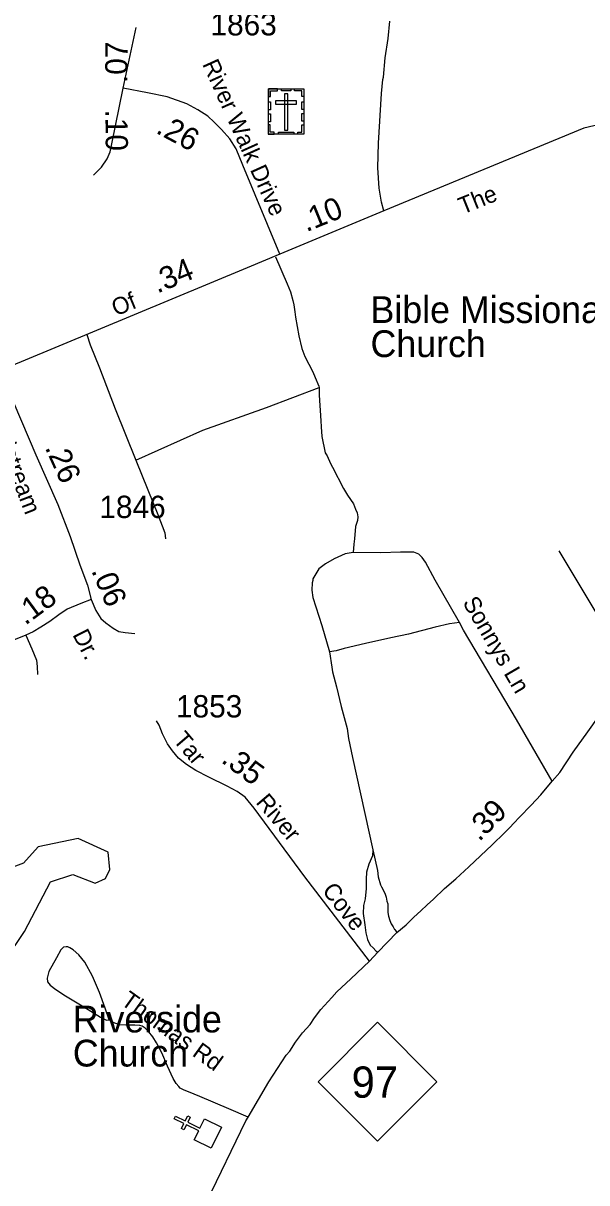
# Model space of a CAD drawing. Extents: x 2220236 to 2384410, y 720751 to 894131.
# Drawn here: x 2329960 to 2333123, y 774971 to 781470 of the extents above; entities that cross this region are included whole.
import ezdxf

# ---------------------------------------------------------------- set-up
doc = ezdxf.new("R2010")
doc.units = 0
for name, color, linetype in [('Exist Cultural Cemetery CELL', 7, 'Continuous'), ('Exist Cultural Church CELL', 7, 'Continuous'), ('Exist Cultural Church Label', 7, 'Continuous'), ('Exist Hydrographic Lake Shore', 7, 'Continuous'), ('Exist Road Non-System Type 51', 7, 'Continuous'), ('Exist Road Non-System Type 51 Label', 7, 'Continuous'), ('Exist Road Primary NC Attributed', 7, 'Continuous'), ('Exist Road Primary NC Service Mileage Hundredths English Label', 7, 'Continuous'), ('Exist Road Primary NC Shield CELL', 7, 'Continuous'), ('Exist Road Primary NC Shield Number Label', 7, 'Continuous'), ('Exist Road Secondary Mileage Hundredths English Label', 7, 'Continuous'), ('Exist Road Secondary Type 51 Attributed', 7, 'Continuous'), ('Exist Road Secondary Type 51 Label', 7, 'Continuous'), ('Exist Road Secondary Type 51 Number Label', 7, 'Continuous')]:
    doc.layers.add(name, color=color, linetype=linetype)

msp = doc.modelspace()

# ---------------------------------------------------------------- linework, layer by layer
at = {"layer": 'Exist Cultural Cemetery CELL'}
for points in [[(2331336, 781103.1), (2331535.1, 781103.1), (2331535.1, 780848.5), (2331336, 780848.5)], [(2331336, 781059.8), (2331347.3, 781059.8), (2331347.3, 781092), (2331387.9, 781092), (2331387.9, 781103.1), (2331336, 781103.1)], [(2331410.1, 781103.1), (2331461.9, 781103.1), (2331461.9, 781091.7), (2331410.1, 781091.7)], [(2331445, 781073.8), (2331426.3, 781073.8), (2331426.3, 780871), (2331445, 780871)], [(2331535.1, 781059.7), (2331523.8, 781059.7), (2331523.8, 781091.9), (2331483.2, 781091.9), (2331483.2, 781103.1), (2331535.1, 781103.1)], [(2331336, 780985.6), (2331336, 781028.9), (2331347.4, 781028.9), (2331347.4, 780985.6)], [(2331376.8, 781035), (2331376.8, 781016.4), (2331494.5, 781016.4), (2331494.5, 781035)], [(2331523.7, 780986.7), (2331523.7, 781030), (2331535.1, 781030), (2331535.1, 780986.7)], [(2331336, 780918.4), (2331336, 780961.7), (2331347.3, 780961.7), (2331347.3, 780918.4)], [(2331523.7, 780920.7), (2331523.7, 780964.1), (2331535.1, 780964.1), (2331535.1, 780920.7)], [(2331369.1, 780848.5), (2331369.1, 780860), (2331347.1, 780860), (2331347.1, 780900.4), (2331335.9, 780900.4), (2331335.9, 780848.5)], [(2331393.4, 780860), (2331478.3, 780860), (2331478.3, 780848.6), (2331393.4, 780848.6)], [(2331501.9, 780848.5), (2331501.9, 780860), (2331523.9, 780860), (2331523.9, 780900.4), (2331535.1, 780900.4), (2331535.1, 780848.5)]]:
    msp.add_lwpolyline(points, close=True, dxfattribs=at)
at = {"layer": 'Exist Cultural Church CELL'}
msp.add_lwpolyline([(2330920.2, 775211.9), (2330945.1, 775263.2), (2330876.7, 775296.6), (2330862.6, 775267.8), (2330848.3, 775274.8), (2330862.3, 775303.6), (2330808.3, 775329.9), (2330815.3, 775344.4), (2330869.4, 775318), (2330883.4, 775346.7), (2330897.8, 775339.7), (2330883.7, 775311), (2330952.1, 775277.6), (2330977.5, 775329.3), (2331073.2, 775282.6), (2331015.9, 775165.2)], close=True, dxfattribs=at)
at = {"layer": 'Exist Hydrographic Lake Shore'}
msp.add_lwpolyline([(2329745, 776051.7), (2329967, 776379.1), (2330114.1, 776657.5), (2330238.1, 776698.7), (2330364, 776651.3), (2330422.1, 776676.7), (2330446.1, 776726.9), (2330437, 776825), (2330269.1, 776900.2), (2330045, 776854.9), (2329962.9, 776762.9), (2329805.1, 776704)], dxfattribs=at)
at = {"layer": 'Exist Road Non-System Type 51'}
msp.add_line((2332045, 776391), (2332056.4, 776374.2), dxfattribs=at)
for points in [[(2331375.6, 780160.2), (2331442.6, 780008.8), (2331460.2, 779965.6), (2331474.2, 779915.3), (2331478.4, 779891.4), (2331485, 779853.3), (2331489.2, 779823.5), (2331507.7, 779719), (2331523.7, 779647.3), (2331540.6, 779602.7), (2331585.9, 779515.7), (2331598.3, 779484.3), (2331618.9, 779435.2), (2331621.1, 779429)], [(2330317.1, 779724.8), (2330336.1, 779667.9), (2330387.8, 779538.6), (2330477.3, 779309.4), (2330592.8, 779021.5)], [(2330592.8, 779021.5), (2330968.3, 779188.7), (2331324.8, 779316.3), (2331621.1, 779429)], [(2331621.1, 779429), (2331621.7, 779385.3), (2331631.4, 779241.3), (2331631.8, 779207.3), (2331636.4, 779153.3), (2331655.3, 779061.6), (2331665.6, 779045.6), (2331684, 779002), (2331696.2, 778982.1), (2331757.5, 778862.7), (2331779.8, 778825), (2331813.4, 778776.6), (2331825.7, 778746.7), (2331833.8, 778726.3), (2331837.9, 778704.5), (2331836.5, 778682.7), (2331825.7, 778648.7), (2331820.2, 778580.7), (2331816.1, 778550.8), (2331812.1, 778503.9)], [(2330592.8, 779021.5), (2330659.9, 778854.3), (2330715.1, 778717.3), (2330754.7, 778613.9), (2330759.8, 778581.1)], [(2331812.1, 778503.9), (2331767.2, 778495.7), (2331706, 778468.5), (2331657.1, 778439.9), (2331618.5, 778411.5), (2331586.4, 778357), (2331585, 778346.1), (2331582.3, 778333.8), (2331581, 778293), (2331586.4, 778252.2), (2331636.7, 778094.4), (2331679.1, 777947.5)], [(2332408.1, 778110.8), (2332271.5, 778348.8), (2332218.5, 778449.5), (2332199.5, 778476.7), (2332180.5, 778494.4), (2332153.3, 778505.2), (2332131.5, 778506.6), (2332077.1, 778505.2), (2331967, 778502.5), (2331812.1, 778503.9)], [(2333591, 778165.2), (2333561.3, 778182.7), (2333543.7, 778189.3), (2333537.1, 778188.2), (2333527.3, 778181.6), (2333431.2, 778025.1), (2333403.7, 777977.8), (2333374.1, 777942.7), (2333356.6, 777930.5), (2333348.8, 777925.1), (2333338.9, 777926.2), (2333325.8, 777920.7), (2333314.8, 777930.6), (2333294.4, 777965.8), (2333270, 778009.4), (2332968.7, 778513.9)], [(2332408.1, 778110.8), (2332352, 778104), (2332271.8, 778084.9), (2332122.3, 778046.8), (2332023, 778025.1), (2331881.7, 777993.8), (2331762, 777965.2), (2331717.2, 777953), (2331679.1, 777947.5)], [(2332928.1, 777222.5), (2332728.3, 777568), (2332431.9, 778069.3), (2332408.1, 778110.8)], [(2329974.7, 778040), (2330009.3, 777964.1), (2330035.9, 777900.2), (2330038.6, 777865.6), (2330041.3, 777820.3)], [(2331679.1, 777947.5), (2331692.4, 777860.4), (2331696.7, 777834.5), (2331718.3, 777751.7), (2331744.1, 777640.1), (2331778, 777517.5), (2331786.5, 777461.7), (2331807.7, 777354.1), (2331922.6, 776837.4)], [(2331922.6, 776837.4), (2331920.1, 776803.3), (2331900.4, 776756.5), (2331886.1, 776712.7), (2331884.3, 776673.1), (2331884.3, 776620.9), (2331878.9, 776563.3), (2331869.9, 776525.5), (2331868.1, 776480.5), (2331877.1, 776417.5), (2331882.5, 776372.5), (2331893.3, 776334.7), (2331907.7, 776302.3), (2331923.9, 776287.9), (2331940.1, 776271.6), (2331951.3, 776263.7)], [(2331922.6, 776837.4), (2331948.3, 776721.8), (2331952.8, 776685.8), (2331965.2, 776642.1), (2331971.3, 776630.1), (2331989.7, 776595), (2331998.1, 776572.4), (2332000.2, 776550.5), (2332006.4, 776534.5), (2332007, 776486.6), (2332011.2, 776466.5), (2332017.8, 776440.8), (2332025.9, 776422.7), (2332035.9, 776405.5), (2332043.5, 776390.2)], [(2330443.2, 775885.5), (2330419.8, 775950.3), (2330389.2, 776038.5), (2330349.6, 776128.5), (2330306.4, 776207.7), (2330272.2, 776249.1), (2330241.6, 776276.1), (2330221.9, 776288.8), (2330211.1, 776294.2), (2330202.1, 776294.2), (2330185.9, 776292.4), (2330171.5, 776276.1), (2330148.1, 776232.9), (2330104.9, 776155.5), (2330094.1, 776117.7), (2330097.7, 776097.9), (2330112.1, 776079.9), (2330144.5, 776054.7), (2330198.5, 776018.7), (2330301, 775957.5), (2330394.6, 775899.9), (2330427, 775881.9), (2330443.2, 775885.5)], [(2331222.1, 775339.2), (2331114.3, 775386.8), (2330952.3, 775455.2), (2330887.6, 775480.4), (2330864.2, 775491.2), (2330840.8, 775502), (2330833.6, 775511), (2330819.2, 775527.2), (2330801.2, 775556), (2330770.6, 775624.4), (2330738.2, 775700), (2330709.4, 775755.8), (2330687.8, 775790.1), (2330664.5, 775818.9), (2330644.7, 775838.7), (2330628.5, 775849.5), (2330614.1, 775853.1), (2330587.1, 775854.9), (2330560.1, 775854.9), (2330536.7, 775854.9), (2330502.5, 775856.7), (2330475.5, 775865.7), (2330455.8, 775874.7), (2330443.2, 775885.5)]]:
    msp.add_lwpolyline(points, dxfattribs=at)
at = {"layer": 'Exist Road Primary NC Attributed'}
for points in [[(2331904.1, 776214), (2331951.3, 776263.7), (2332056.4, 776374.2), (2332109.8, 776417.3), (2332151.9, 776460.8), (2332191.3, 776494.8), (2332228, 776528.8), (2332263.4, 776561.4), (2332324.5, 776621.3), (2332388.4, 776675.7), (2332460.5, 776743), (2332592.3, 776865.5), (2332660.3, 776932.1), (2332690.2, 776962), (2332713.3, 776986.5), (2332744.6, 777020.5), (2332811.2, 777087.9), (2332864.2, 777146.4), (2332928.1, 777222.5), (2332970.8, 777271.1), (2333046.3, 777384.3), (2333129.6, 777498.1), (2333298.9, 777737.9)], [(2330445.1, 773713.1), (2330598, 773996.7), (2330777.7, 774388.5), (2330855.8, 774573.1), (2330866.3, 774595.9), (2330990.5, 774866.4), (2331209.8, 775318.4), (2331222.1, 775339.2), (2331339.5, 775537.8), (2331435.8, 775686.8), (2331457.5, 775709.1), (2331488.9, 775759.4), (2331528.4, 775811.6), (2331569.9, 775858.1), (2331595.5, 775896.4), (2331630.8, 775942.8), (2331691.8, 776010.6), (2331719.8, 776041.7), (2331799.8, 776115), (2331904.1, 776214)]]:
    msp.add_lwpolyline(points, dxfattribs=at)
at = {"layer": 'Exist Road Primary NC Shield CELL'}
msp.add_lwpolyline([(2331616.1, 775538), (2331949.1, 775871), (2332282.1, 775538), (2331949.1, 775205)], close=True, dxfattribs=at)
at = {"layer": 'Exist Road Secondary Type 51 Attributed'}
for points in [[(2330522.3, 781106.7), (2330593.6, 781447)], [(2331985, 780419.4), (2331970.5, 780467.4), (2331957.2, 780546.3), (2331950, 780660), (2331953.3, 780798.6), (2331971.6, 781076), (2331978.8, 781154.1), (2331982.7, 781168.1), (2331991.5, 781276.3), (2332008.2, 781384.4), (2332017.3, 781482.4)], [(2330355.8, 780619.4), (2330400.3, 780663.2), (2330432.1, 780710.5), (2330447.6, 780748.8), (2330458.2, 780793.7), (2330522.3, 781106.7)], [(2331400.6, 780175.5), (2331193.5, 780675.4), (2331155.6, 780765.9), (2331119.7, 780821.4), (2331072.4, 780875.2), (2331031.6, 780916), (2330995.7, 780948.7), (2330940.7, 780985.4), (2330878.7, 781018.8), (2330767.7, 781057.1), (2330658.4, 781080), (2330522.3, 781106.7)], [(2334401.3, 780175.6), (2334301.5, 780217.3), (2334191.6, 780259), (2334010.9, 780345), (2333880.8, 780438.5), (2333782.2, 780532.1), (2333683.7, 780608), (2333496, 780755.2), (2333435.4, 780802), (2333358.3, 780851.3), (2333307, 780886.5), (2333267.3, 780898.1), (2333233.2, 780900.6), (2333204.2, 780903.2), (2333163, 780895.2), (2333106.7, 780882.2), (2331985, 780419.4)], [(2331985, 780419.4), (2331400.6, 780175.5)], [(2331400.6, 780175.5), (2331216.8, 780098.7), (2329949.9, 779572.4), (2329831.5, 779523.6)], [(2329831.5, 779523.6), (2329908.2, 779341), (2330030.6, 779050.7), (2330155.7, 778773.7), (2330224.9, 778592.6), (2330278.1, 778435.5), (2330320.7, 778321), (2330342, 778241.1)], [(2330342, 778241.1), (2330283.4, 778218.5), (2330206.3, 778186.5), (2330161, 778154.6), (2330110.5, 778117.3), (2330059.9, 778085.3), (2330017.3, 778058.7), (2329974.7, 778040), (2329916.2, 778016.1), (2329865.6, 778000.1), (2329817.7, 778000.1), (2329780.4, 778002.8), (2329745.9, 778016.1), (2329711.3, 778042.7), (2329695.3, 778072), (2329674, 778106.6), (2329663.3, 778162.5), (2329652.7, 778210.5), (2329636.7, 778287.7)], [(2330342, 778241.1), (2330368.6, 778178.5), (2330395.2, 778133.3), (2330424.5, 778109.3), (2330464.4, 778080), (2330496.4, 778061.4), (2330533.6, 778056), (2330586.8, 778050.7)], [(2331904.1, 776214), (2331540.7, 776686.6), (2331256.4, 777071.9), (2331206, 777132.2), (2331161, 777164.6), (2331105.3, 777195.2), (2331002.7, 777243.8), (2330928.9, 777281.6), (2330876.8, 777315.9), (2330831.8, 777351.9), (2330797.6, 777391.5), (2330770.6, 777431.1), (2330741.8, 777486.9), (2330723.8, 777535.5), (2330707.6, 777560.7)]]:
    msp.add_lwpolyline(points, dxfattribs=at)

# ---------------------------------------------------------------- texts
at = {"layer": 'Exist Cultural Church Label'}
for s, p in [('Bible Missionary', (2331909.4, 779790)), ('Church', (2331909.4, 779599)), ('Riverside', (2330239, 775814.1)), ('Church', (2330239, 775623.1))]:
    msp.add_text(s, height=150, dxfattribs=at).set_placement(p)
at = {"layer": 'Exist Road Non-System Type 51 Label'}
for s, rotation, p in [('Sonnys Ln', 300.23968, (2332423.4, 778223.6)), ('Thomas Rd', 324.29459, (2330502.3, 775975.3))]:
    msp.add_text(s, height=95, rotation=rotation, dxfattribs=at).set_placement(p)
at = {"layer": 'Exist Road Primary NC Service Mileage Hundredths English Label'}
msp.add_text('.39', height=125, rotation=45.01807, dxfattribs=at).set_placement((2332519.9, 776880.1))
at = {"layer": 'Exist Road Primary NC Shield Number Label'}
msp.add_text('97', height=175, dxfattribs=at).set_placement((2331803.3, 775448.3))
at = {"layer": 'Exist Road Secondary Mileage Hundredths English Label'}
for s, rotation, p in [('.07', 89.85147, (2330545.4, 781134.7)), ('.10', 270.52187, (2330421.6, 780986.1)), ('.26', 331.89732, (2330699.4, 780857.9)), ('.10', 22.17976, (2331549.4, 780298.6)), ('.34', 22.40521, (2330713, 779954.6)), ('.26', 294.30558, (2330080.5, 779092.1)), ('.06', 293.03853, (2330341, 778402.5)), ('.18', 36.40163, (2329972.2, 778093)), ('.35', 323.33284, (2331065.9, 777331.5))]:
    msp.add_text(s, height=125, rotation=rotation, dxfattribs=at).set_placement(p)
at = {"layer": 'Exist Road Secondary Type 51 Label'}
for s, rotation, p in [('River Walk Drive', 294.34485, (2330963.9, 781241.4)), ('The', 21.85115, (2332426.2, 780397.5)), ('Of', 22.4052, (2330480.6, 779826.7)), ('Fieldstream', 290.93707, (2329737, 779329.4)), ('Dr.', 297.16667, (2330235.3, 778043.7)), ('Tar', 310.48949, (2330797.3, 777450.4)), ('River', 310.33196, (2331262.2, 777102.1)), ('Cove', 307.73472, (2331634.2, 776608.2))]:
    msp.add_text(s, height=95, rotation=rotation, dxfattribs=at).set_placement(p)
at = {"layer": 'Exist Road Secondary Type 51 Number Label'}
for s, p in [('1863', (2331011.4, 781401.7)), ('1846', (2330387.9, 778697.2)), ('1853', (2330817.9, 777579.5))]:
    msp.add_text(s, height=125, dxfattribs=at).set_placement(p)

doc.saveas('drawing.dxf')
